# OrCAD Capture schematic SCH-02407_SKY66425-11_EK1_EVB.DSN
size B; title: SKY66425-11 EK1 EVB; rev: A2; company: SKYWORKS SOLUTIONS, INC.; note: SCH-02407; note: 1135 INNOVATION DRIVE; note: OTTAWA, ONTARIO CANADA
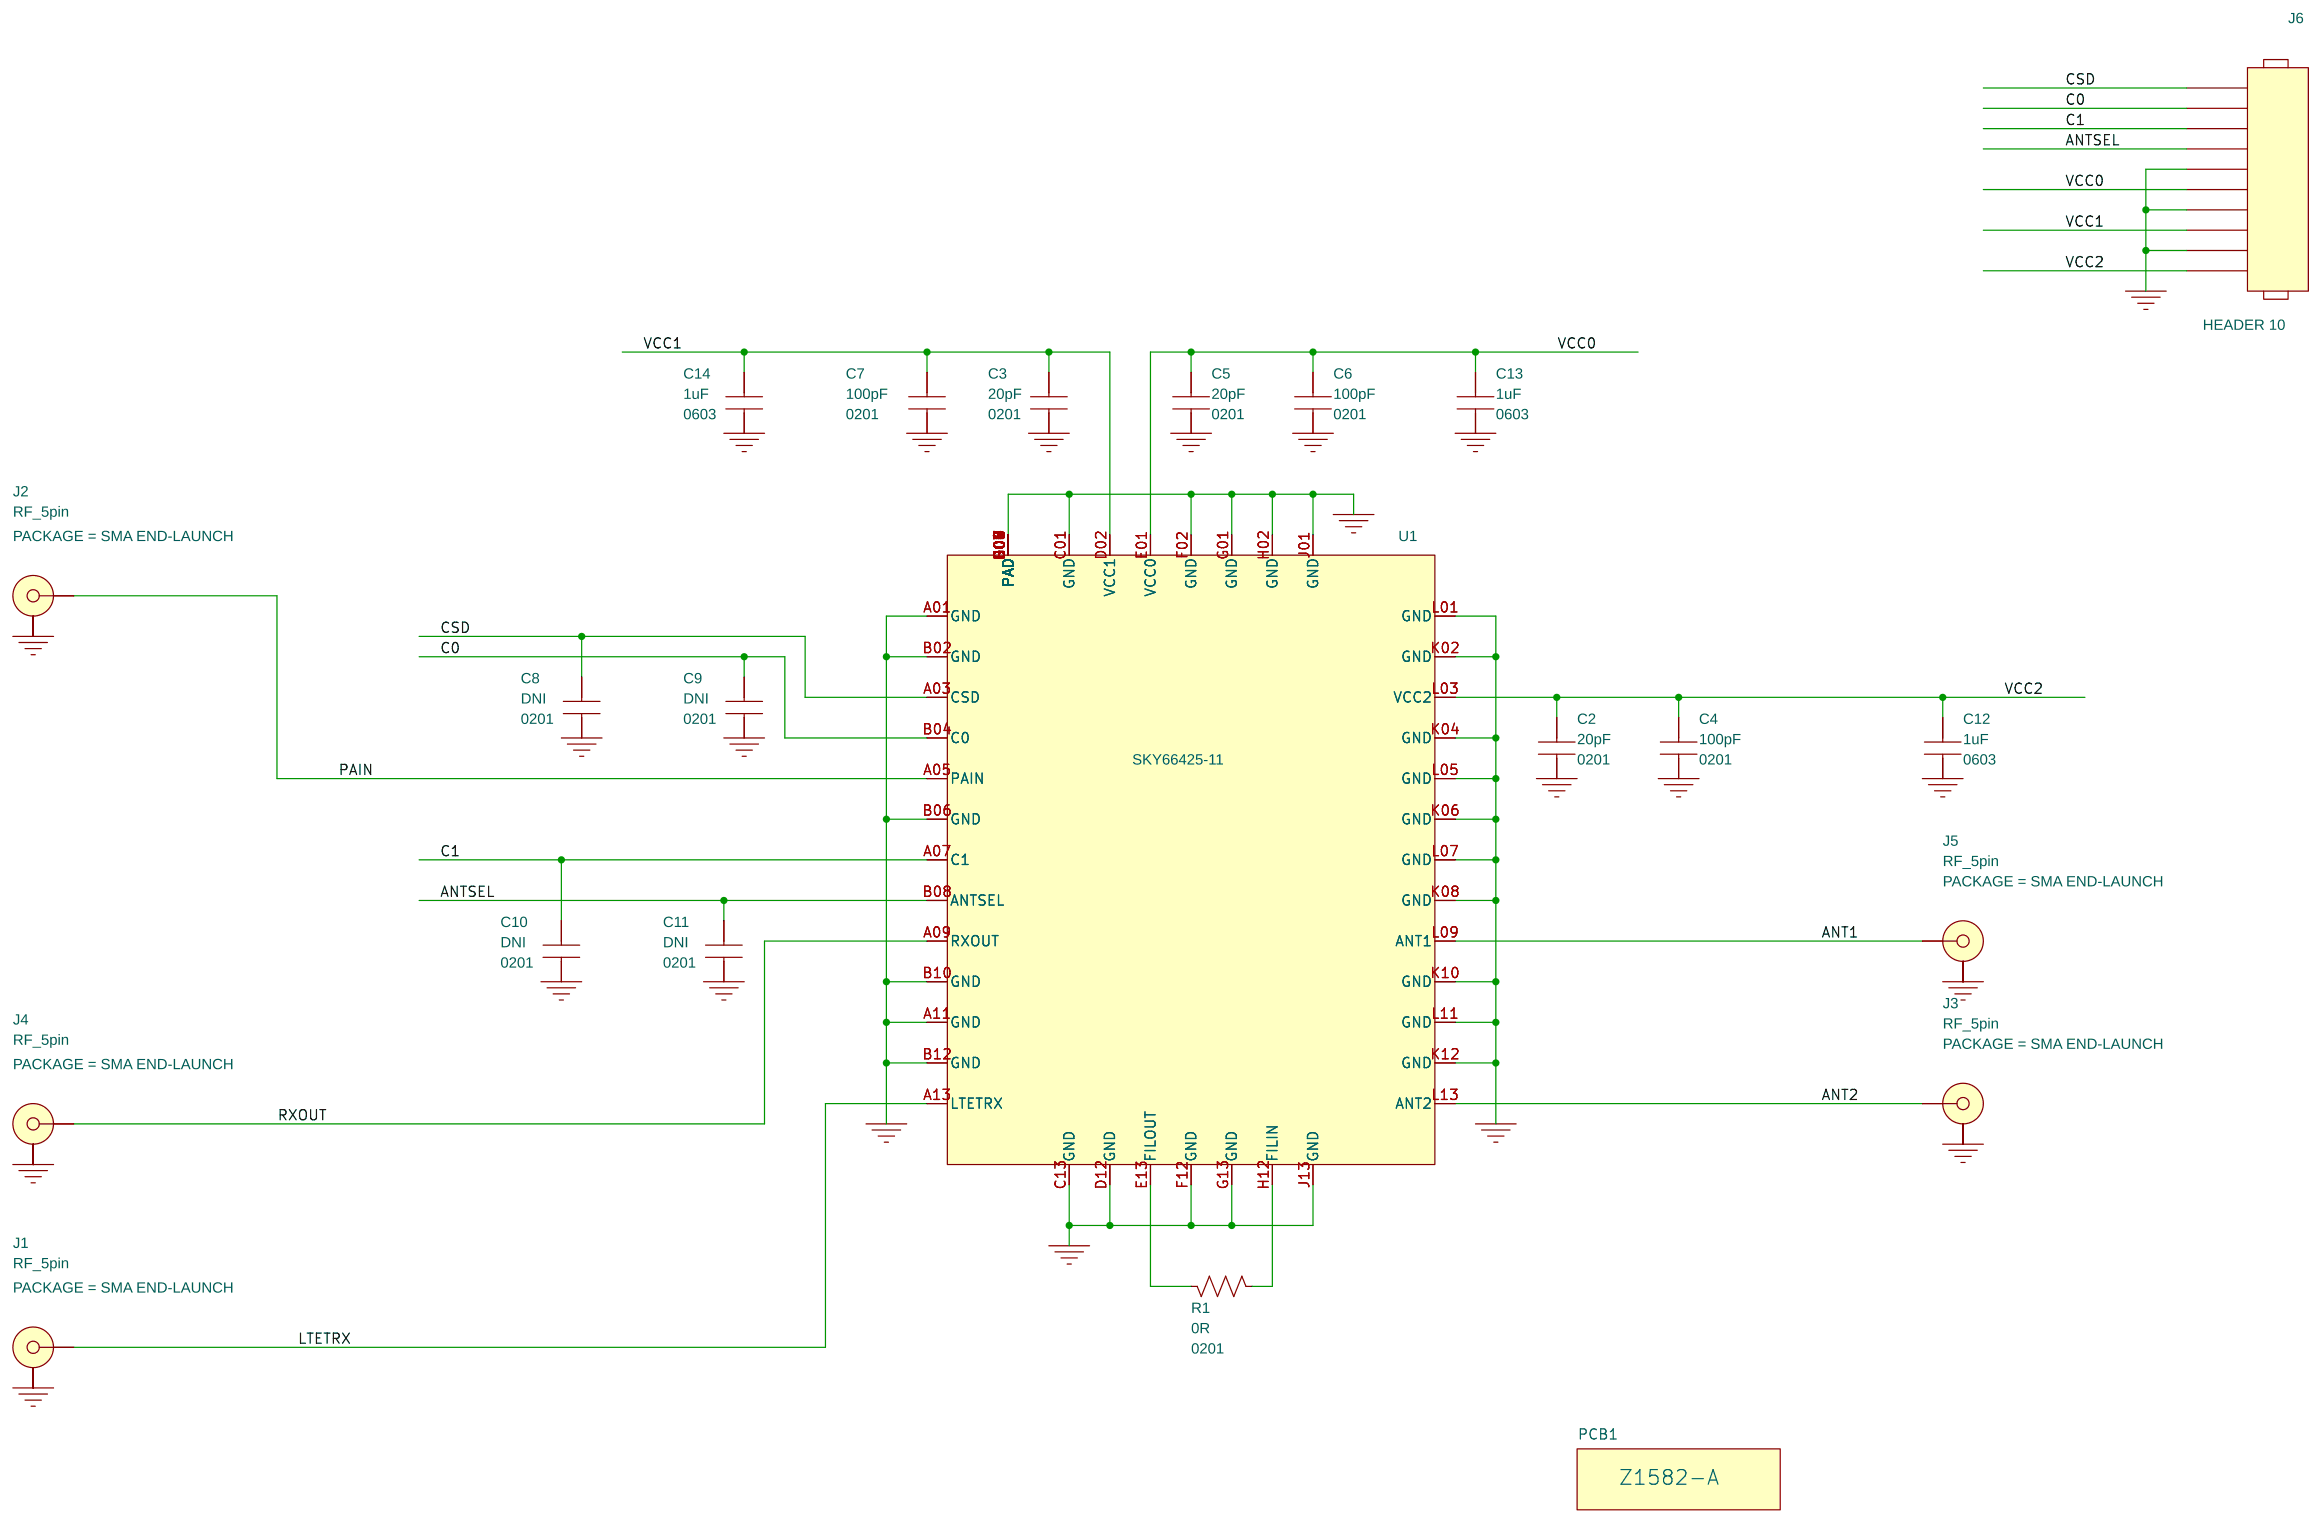
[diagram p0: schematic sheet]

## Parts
C2  20pF  [SMDC600X300]
C3  20pF  [SMDC600X300]
C4  100pF  [SMDC600X300]
C5  20pF  [SMDC600X300]
C6  100pF  [SMDC600X300]
C7  100pF  [SMDC600X300]
C8  DNI  [SMDC600X300]
C9  DNI  [SMDC600X300]
C10  DNI  [SMDC600X300]
C11  DNI  [SMDC600X300]
C12  1uF  [SMDC1600X800]
C13  1uF  [SMDC1600X800]
C14  1uF  [SMDC1600X800]
J1  RF_5pin  [sma_cpwg_442_236]
J2  RF_5pin  [sma_cpwg_442_236]
J3  RF_5pin  [sma_cpwg_442_236]
J4  RF_5pin  [sma_cpwg_442_236]
J5  RF_5pin  [sma_cpwg_442_236]
J6  HEADER 10  [TSW-110-07-G-S]
PCB1  Z1582-A
R1  0R  [SMDC600X300]
U1  SKY66425-11  [SP03-D512_01]

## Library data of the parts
C2 C3 C5 = C: Multilayer Ceramic; Manufacturer: MURATA; Manufacturer_PN: GRM0335C1E200JD01; Package: 0201
C4 C6 C7 = C: Multilayer Ceramic; Manufacturer: MURATA; Manufacturer_PN: GRM033R71H101KA12; Package: 0201
C8-C11 = C: Package: 0201
C12-C14 = C: Multilayer Ceramic; Manufacturer: MURATA; Manufacturer_PN: GRM188R71A105KA61; Package: 0603
J1-J5 = RF_5pin: CONNECTOR, SMA END-LAUNCH; Manufacturer: SPC/Multicomp; Manufacturer_PN: R19_070-18-0032210MM; PACKAGE: SMA END-LAUNCH
J6 = HEADER_10: 1X10 Header Verticle; Manufacturer: Samtec; Package: 100mil
PCB1 = PCB_0: PCB; Manufacturer: Skyworks
R1 = R: Thick Film Chip Resistor; Manufacturer: Panasonic; Manufacturer_PN: ERJ1GE0R00; Package: 0201
U1 = SKY66425-11: Manufacturer: Skyworks Solutions Inc.

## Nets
GND: C2.2 C3.2 C4.2 C5.2 C6.2 C7.2 C8.2 C9.2 C10.2 C11.2 C12.2 C13.2 C14.2 J1.2(GND) J1.3(GND) J1.4(GND) J1.5(GND) J2.2(GND) J2.3(GND) J2.4(GND) J2.5(GND) J3.2(GND) J3.3(GND) J3.4(GND) J3.5(GND) J4.2(GND) J4.3(GND) J4.4(GND) J4.5(GND) J5.2(GND) J5.3(GND) J5.4(GND) J5.5(GND) J6.5 J6.7 J6.9 U1.A01(GND) U1.A11(GND) U1.B02(GND) U1.B06(GND) U1.B10(GND) U1.B12(GND) U1.C01(GND) U1.C13(GND) U1.D04(PAD) U1.D05(PAD) U1.D06(PAD) U1.D07(PAD) U1.D08(PAD) U1.D09(PAD) U1.D12(GND) U1.E04(PAD) U1.E05(PAD) U1.E06(PAD) U1.E07(PAD) U1.E08(PAD) U1.E09(PAD) U1.F02(GND) U1.F12(GND) U1.G01(GND) U1.G04(PAD) U1.G05(PAD) U1.G06(PAD) U1.G07(PAD) U1.G08(PAD) U1.G09(PAD) U1.G13(GND) U1.H02(GND) U1.H04(PAD) U1.H05(PAD) U1.H06(PAD) U1.H07(PAD) U1.H08(PAD) U1.H09(PAD) U1.J01(GND) U1.J13(GND) U1.K02(GND) U1.K04(GND) U1.K06(GND) U1.K08(GND) U1.K10(GND) U1.K12(GND) U1.L01(GND) U1.L05(GND) U1.L07(GND) U1.L11(GND)
VCC0: C5.1 C6.1 C13.1 J6.6 U1.E01(VCC0)
VCC1: C3.1 C7.1 C14.1 J6.8 U1.D02(VCC1)
VCC2: C2.1 C4.1 C12.1 J6.10 U1.L03(VCC2)
ANT1: J5.1(SIG) U1.L09(ANT1)
ANT2: J3.1(SIG) U1.L13(ANT2)
ANTSEL: C11.1 J6.4 U1.B08(ANTSEL)
C0: C9.1 J6.2 U1.B04(C0)
C1: C10.1 J6.3 U1.A07(C1)
CSD: C8.1 J6.1 U1.A03(CSD)
LTETRX: J1.1(SIG) U1.A13(LTETRX)
PAIN: J2.1(SIG) U1.A05(PAIN)
RXOUT: J4.1(SIG) U1.A09(RXOUT)
N13114708: R1.2 U1.H12(FILIN)
N13124264: R1.1 U1.E13(FILOUT)
